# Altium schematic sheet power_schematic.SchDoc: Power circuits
size A3; Organization: Altium Limited; Address1: L3, 12a Rodborough Rd; Address2: Frenchs Forest; Address3: NSW; Address4: Australia 2086; DocumentNumber: 6; SheetNumber: 6; SheetTotal: 8
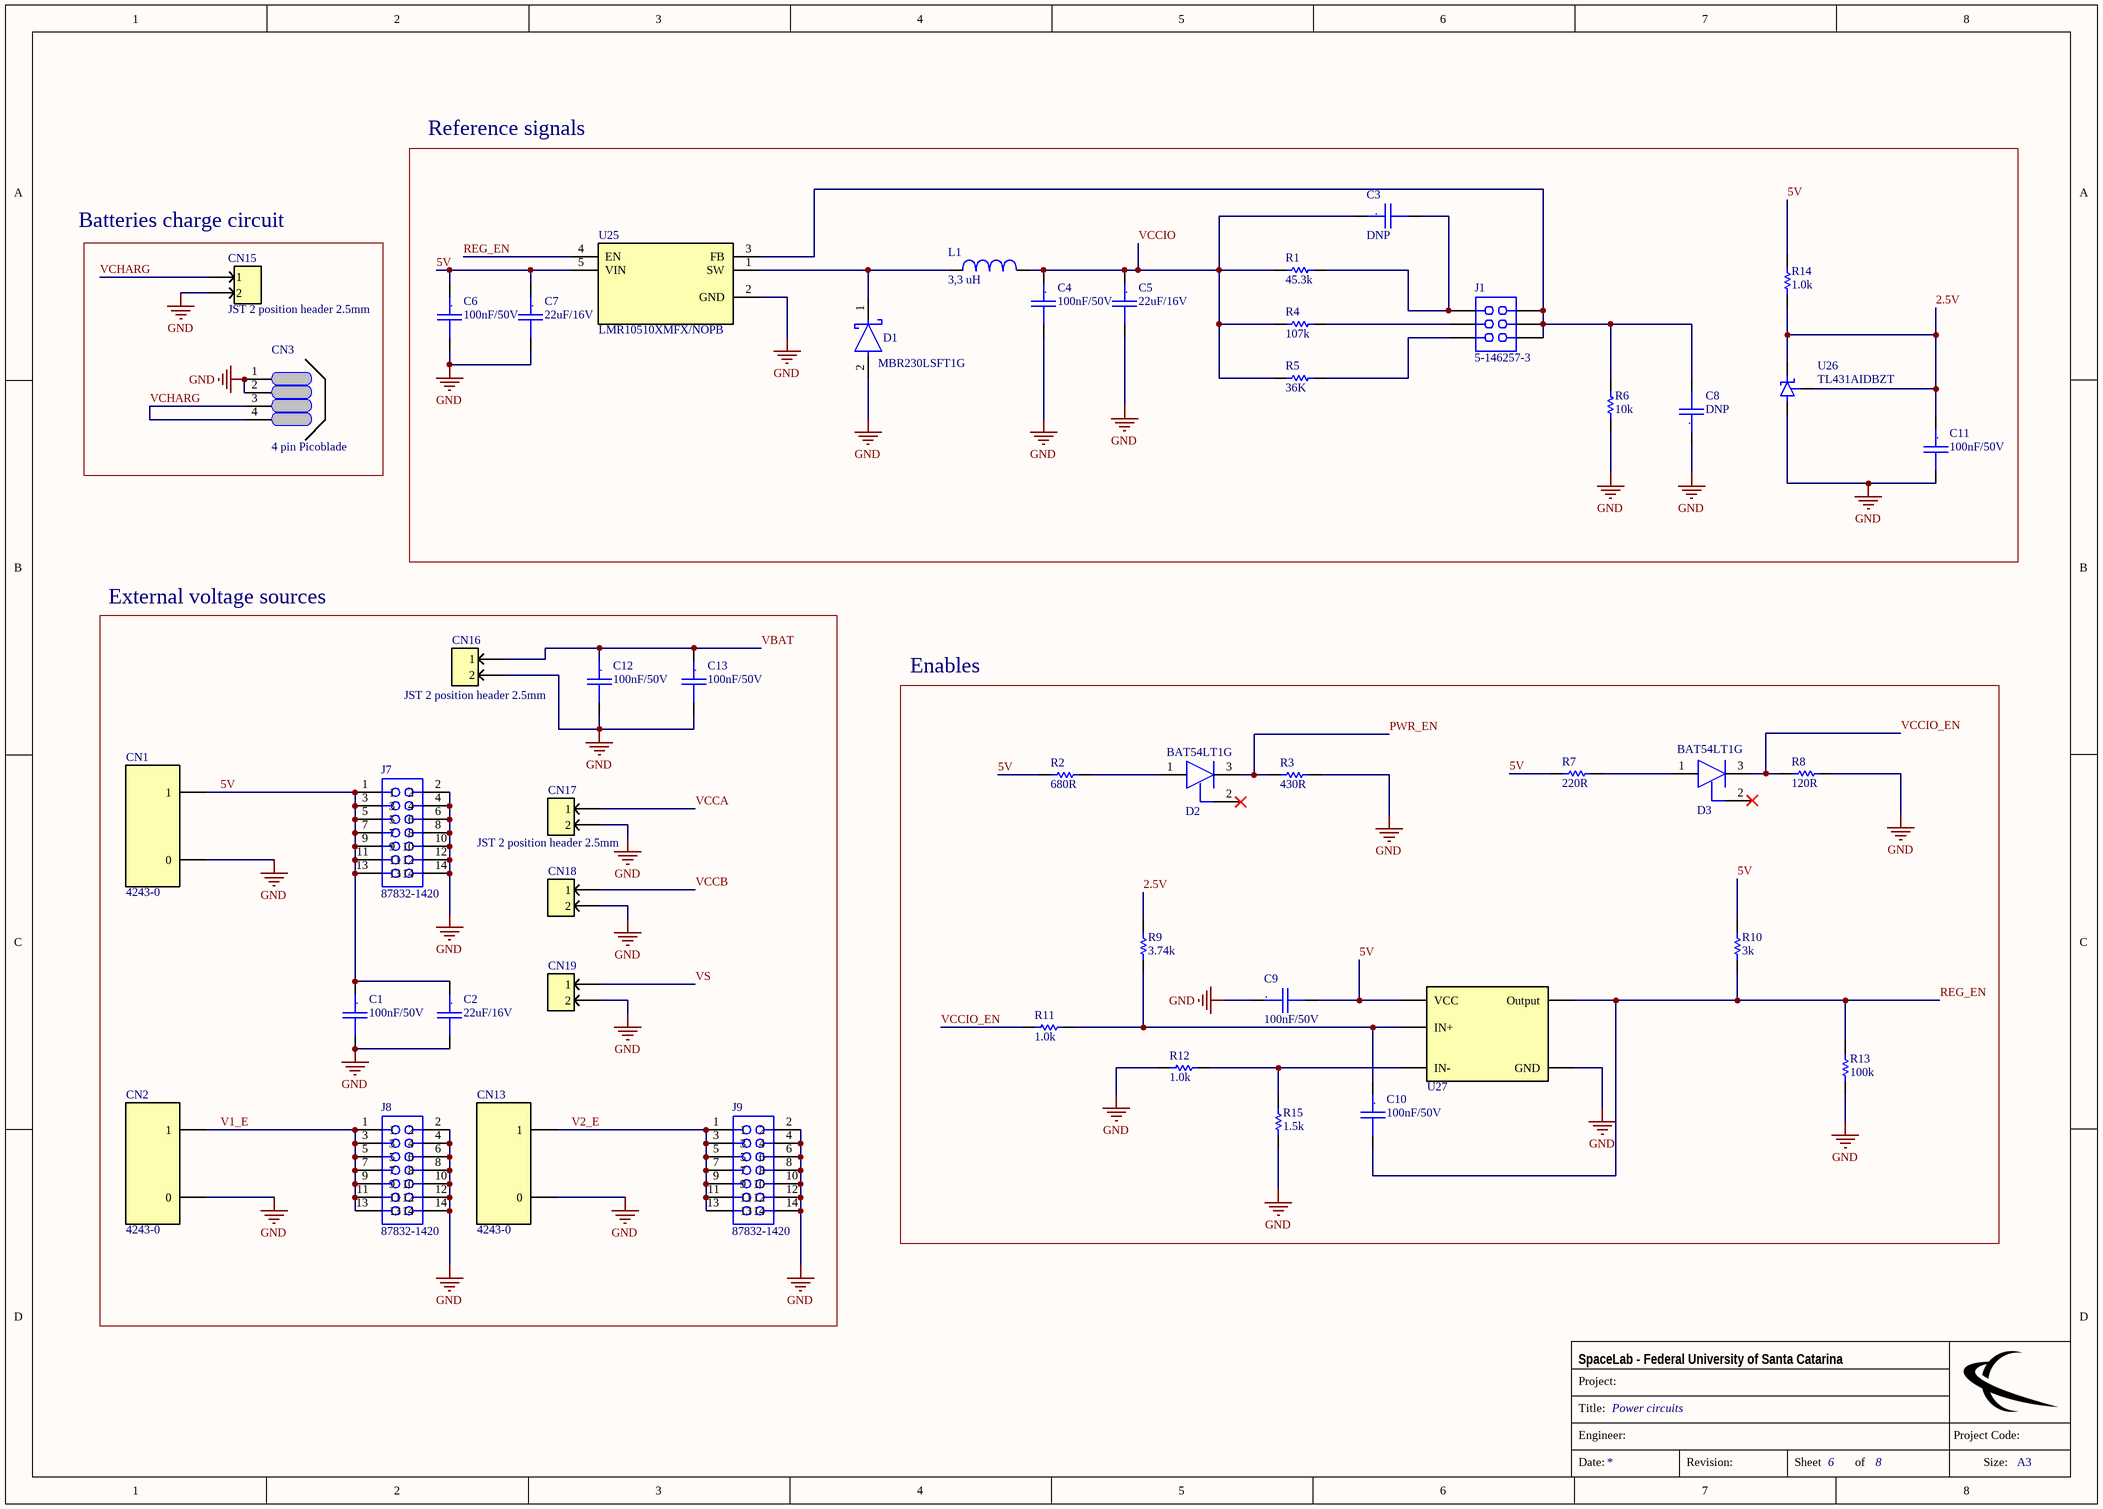
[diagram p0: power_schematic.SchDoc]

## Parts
C1  100nF/50V  [CC0603]
C2  22uF/16V  [CC1210]
C3  DNP  [CC0805]
C4  100nF/50V  [CC0603]
C5  22uF/16V  [CC1210]
C6  100nF/50V  [CC0603]
C7  22uF/16V  [CC1210]
C8  DNP  [CC0805]
C9  100nF/50V  [CC0603]
C10  100nF/50V  [CC0603]
C11  100nF/50V  [CC0603]
C12  100nF/50V  [CC0603]
C13  100nF/50V  [CC0603]
CN1  4243-0  [4243-0]
CN2  4243-0  [4243-0]
CN3  4 pin Picoblade  [PICO BLADE 0533980471]
CN13  4243-0  [4243-0]
CN15  JST 2 position header 2.5mm  [B2B-XH-A-M(LF)(SN)]
CN16  JST 2 position header 2.5mm  [B2B-XH-A-M(LF)(SN)]
CN17  JST 2 position header 2.5mm  [B2B-XH-A-M(LF)(SN)]
CN18  JST 2 position header 2.5mm  [B2B-XH-A-M(LF)(SN)]  (value not drawn)
CN19  JST 2 position header 2.5mm  [B2B-XH-A-M(LF)(SN)]  (value not drawn)
D1  MBR230LSFT1G  [On_Semiconductor_498_MFG]
D2  BAT54LT1G  [SOT95P237X112-3N]
D3  BAT54LT1G  [SOT95P237X112-3N]
J1  5-146257-3  [TE_5-146257-3]
J7  87832-1420  [SAMTEC_TSW-107-05-F-D]
J8  87832-1420  [SAMTEC_TSW-107-05-F-D]
J9  87832-1420  [SAMTEC_TSW-107-05-F-D]
L1  3,3 uH  [SRR6038]
R1  45.3k  [0805]
R2  680R  [0805]
R3  430R  [0805]
R4  107k  [0805]
R5  36K  [0805]
R6  10k  [0805]
R7  220R  [0805]
R8  120R  [0805]
R9  3.74k  [0805]
R10  3k  [0805]
R11  1.0k  [0805]
R12  1.0k  [0805]
R13  100k  [0805]
R14  1.0k  [0805]
R15  1.5k  [0805]
U25  LMR10510XMFX/NOPB  [SOT95P280X145-5N]
U26  TL431AIDBZT  [SOT95P237X112-3N]
U27  AP331AWG-7  [SOT95P280X145-5N]  (value not drawn)

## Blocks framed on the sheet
Reference signals: C3-C8 C11 D1 J1 L1 R1 R4-R6 R14 U25 U26
External voltage sources: C1 C2 C12 C13 CN1 CN2 CN13 CN16-CN19 J7-J9
Enables: C9 C10 D2 D3 R2 R3 R7-R13 R15 U27

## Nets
GND: C1.2 C2.2 C4.2 C5.2 C6.2 C7.2 C8.1 C9.1 C11.2 C12.2 C13.2 CN1.0 CN2.0 CN3.1 CN3.2 CN13.0 CN15.2 CN16.2 CN17.2 CN18.2 CN19.2 D1.2(A) J7.2 J7.4 J7.6 J7.8 J7.10 J7.12 J7.14 J8.2 J8.4 J8.6 J8.8 J8.10 J8.12 J8.14 J9.2 J9.4 J9.6 J9.8 J9.10 J9.12 J9.14 R3.1 R6.1 R8.1 R12.2 R13.1 R15.1 U25.2(GND) U26.3(ANODE) U27.2(GND)
2.5V: C11.1 R9.2 R14.1 U26.1(CATHODE) U26.2(REF)
5V: C1.1 C2.1 C6.1 C7.1 C9.2 CN1.1 J7.1 J7.3 J7.5 J7.7 J7.9 J7.11 J7.13 R2.2 R7.2 R10.2 R14.2 U25.5(VIN) U27.5(VCC)
PWR_EN: D2.3(C) R3.2
REG_EN: C10.2 R10.1 R13.2 U25.4(EN) U27.4(Output)
V1_E: CN2.1 J8.1 J8.3 J8.5 J8.7 J8.9 J8.11 J8.13
V2_E: CN13.1 J9.1 J9.3 J9.5 J9.7 J9.9 J9.11 J9.13
VBAT: C12.1 C13.1 CN16.1
VCCA: CN17.1
VCCB: CN18.1
VCCIO: C3.1 C4.1 C5.1 L1.2 R1.2 R4.2 R5.2
VCCIO_EN: D3.3(C) R8.2 R11.2
VCHARG: CN3.3 CN3.4 CN15.1
VS: CN19.1
NetC3_2: C3.2 J1.1 R1.1
NetC8_2: C8.2 J1.2 J1.4 J1.6 R6.2 U25.3(FB)
NetC10_1: C10.1 R9.1 R11.1 U27.3(IN+)
NetD1_1: D1.1(C) L1.1 U25.1(SW)
NetD2_1: D2.1(A) R2.1
NetD3_1: D3.1(A) R7.1
NetJ1_3: J1.3 R4.1
NetJ1_5: J1.5 R5.1
NetR12_1: R12.1 R15.2 U27.1(IN-)

Not connected (* = marked no-connect by the designer): D2 2(NC)*; D3 2(NC)*

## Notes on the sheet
- (near CN15) Batteries charge circuit

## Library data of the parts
C1 C4 C6 C9-C13 = Cap_Cer_X7R_100nF_50V_0603: CAP CER 100nF 50V 10% X7R 0603; Manufacturer Part Number: C0603C104K5RAC3121
C2 C5 C7 = Cap_Cer_X7R_22uF_16V_1210: CAP CER 22uF 16V 10% X7R 1210; Manufacturer Part Number: C3225X7R1C226K250AC
C3 C8 = Cap_DNP_0805: CAP DNP 0805
CN1 CN2 CN13 = 4243-0: POMONA, 4243-0, Binding Post, 4243 Series, 15 A, 60 VDC, Tin Plated Contacts, Brass, Black; Manufacturer: Pomona Electronics; Voltage Rating: 2.5kV; Current Rating: 15A; Voltage Rating (DC): 60V; Voltage Rating (AC): 30V; Insulation: Insulated; Number of Ports: 2; Hole Diameter: 0.1inch; Panel Thickness: 6.35mm
CN3 = 0533980471: 1.25mm Pitch PicoBlade™ Header, Surface Mount, Vertical, 4 Circuits; Manufacturer: Molex; Manufacturer Part Number: 53398-0471; N of Positions: 4; Body Plating: Tin; Gender: Male; Current Rating: 1A; Voltage Rating: 125V; Contact Resistance: 20mR; Insulation Resistance: 100MR; Glow Wire Compliant: Non-compliant
CN15-CN19 = B2B-XH-A-M(LF)(SN): CONN HEADER TOP 2POS 2.5MM GRN; Number of Positions: 2; Connector Type: Male Pin; Pitch: 0.098inch
J1 = 5-146257-3: Header; Breakaway; 0.100 x 0.100 in.; PC Board; Dual; 6; 0.025 in.; 0.12 in.; Product_Type: Connector; Number_of_Positions: 6; MF: TE Connectivity; Centerline_Pitch: 2.54 mm[.1 in]
J7-J9 = 87832-1420: Connector Header Surface Mount 14 position 0.079 _2.00mm_; Manufacturer Part Number: TSW-107-05-F-D; MF: Molex
L1 = 3,3 uH: 3.3ÂµH Shielded Wirewound Inductor 3.5A 20mOhm Max Nonstandard; Manufacturer Part Number: SRR6038-3R3Y; MF: Bourns
R1 = R45.3k_1%_1/10W_0805: RES 45.3K OHM 1/8W 1% 0805; Manufacturer Part Number: RC0805FR-0745K3L
R2 = R680R_1%_1/8W_0805: RES 680R OHM 1/8W 1% 0805; Manufacturer Part Number: CRGCQ0805F680R
R3 = R430R_1%_1/4W_0805: RES 430R OHM 1/8W 0.1% 0805; Manufacturer Part Number: RT0805BRD07430RL
R4 = R107k_1%_1/8W_0805: RES 107K OHM 1/8W 1% 0805; Manufacturer Part Number: RC0805FR-07107KL
R5 = R36K_1%_1/10W_0805: RES 36K OHM 1/8W 0.1% 0805; Manufacturer Part Number: RG2012N-363-B-T5
R6 = R10k_1%_1/8W_0805: RES 10K OHM 1/8W 1%  0805; Manufacturer Part Number: CRCW080510K0FKEA
R7 = R220R_1%_1/8W_0805: RES 220R OHM 1/8W 1% 0805; Manufacturer Part Number: CRCW0805220RFKEA
R8 = R120R_1%_1/4W_0805: RES 120R OHM 1/8W 1% 0805; Manufacturer Part Number: CRGCQ0805F120R
R9 = R3.74k_1%_1/8W_0805: RES 3.74K OHM 1/8W 0.5% 0805; Manufacturer Part Number: RT0805DRE073K74L
R10 = R3.0k_1%_1/8W_0805: RES 3.0K OHM 1/10W 0.1% 0805; Manufacturer Part Number: ERA-6YEB302V
R11 R12 R14 = R1.0k_1%_1/8W_0805: RES 1.0K OHM 1/8W 1% 0805; Manufacturer Part Number: RC0805FR-071KL
R13 = R100k_1%_1/8W_0805: RES 100K OHM 1/8W 1% 0805; Manufacturer Part Number: AC0805FR-13100KL
R15 = R1.5K_1%_1/10W_0805: RES 1.5K OHM 1/10W 0.1% 0805; Manufacturer Part Number: RN73C2A1K5BTDF
U26 = TL431AIDBZT: Shunt Voltage Reference IC 36V Â±1% SOT-23-3; MF: Texas Instruments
